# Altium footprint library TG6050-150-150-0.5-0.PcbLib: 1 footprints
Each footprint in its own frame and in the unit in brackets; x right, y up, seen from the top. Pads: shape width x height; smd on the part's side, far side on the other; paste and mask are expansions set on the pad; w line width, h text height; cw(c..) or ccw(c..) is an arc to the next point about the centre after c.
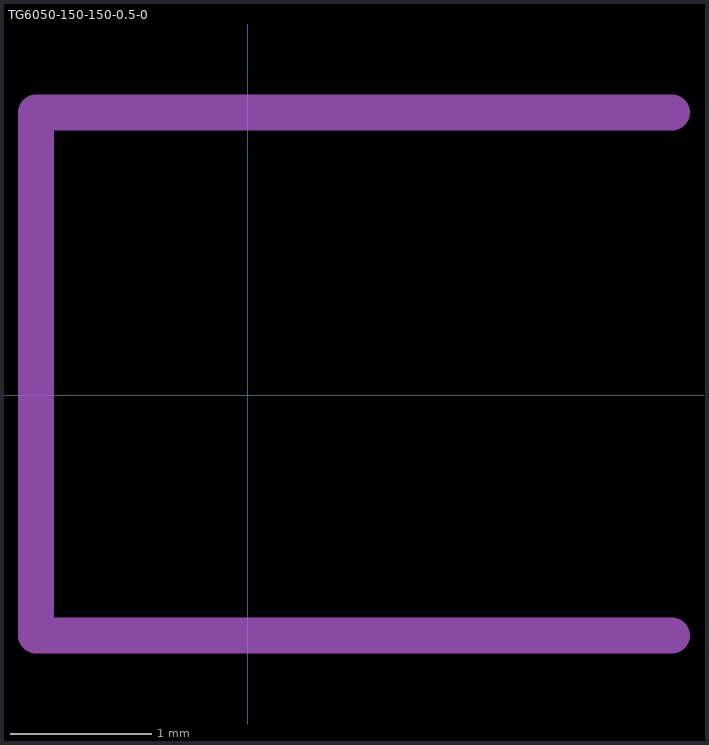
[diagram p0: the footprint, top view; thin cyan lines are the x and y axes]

## TG6050-150-150-0.5-0 [mm] "IGLOBAL TECHNOLOGY TG SERIES SHEET 150X150X0.5MM"
height 1
M5 Assembly Top:
  lines w0.254: 3,-1.7 -1.5,-1.7 -1.5,2 3,2
  text ".Designator" at 0,-0.1 h1.02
